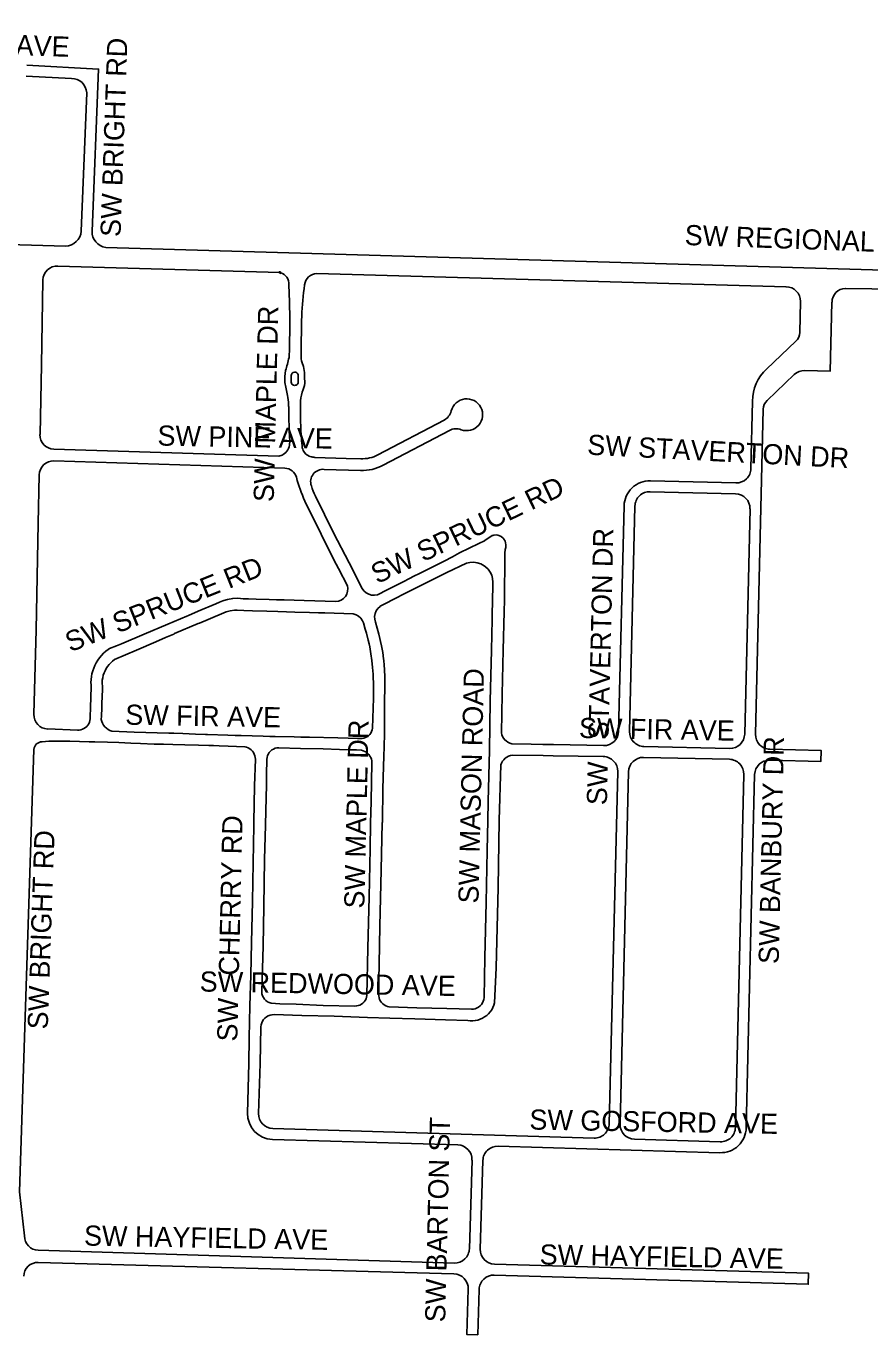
# Model space of a CAD drawing. Extents: x 0 to 712119, y 0 to 761125.
# Drawn here: x 653613 to 655706, y 733634 to 736879 of the extents above; entities that cross this region are included whole.
import ezdxf

# ---------------------------------------------------------------- set-up
doc = ezdxf.new("R2010")
doc.units = 0
doc.layers.add('PAVED ROADS', color=7, linetype='Continuous')
doc.layers.add('street names', color=7, linetype='Continuous')

msp = doc.modelspace()

# ---------------------------------------------------------------- linework, layer by layer
at = {"layer": 'PAVED ROADS'}
for points in [[(657753.4, 736928.9), (657749.7, 736845.1), (657747, 736769.4), (657743.9, 736681.1), (657740.8, 736600.3), (657740.4, 736591.6), (657739.5, 736570.9), (657737.5, 736524.9), (657733.5, 736433.4), (657731.4, 736387.5), (657730.8, 736374.3), (657730.6, 736368.1), (657728.4, 736314.2), (657722.6, 736235.8), (657720.2, 736229), (657715.5, 736222), (657473, 736223.4), (653810.4, 736330.2)], [(653776.8, 736370.3), (653792.4, 736772.4), (653614.5, 736781.6)], [(653613.1, 736754.6), (653725.4, 736748.7)], [(653763.1, 736713.3), (653749.7, 736370.2)], [(653710.8, 736333.1), (652495, 736368.5)], [(653691.7, 736283.5), (653691.7, 736283.6), (654241.9, 736267.6), (654241.8, 736265.5)], [(653647.3, 735865.8), (653650.7, 736039.2), (653654.6, 736249.2)], [(654334, 736265.3), (655497.8, 736232.7)], [(655645, 736228.5), (655646.4, 736228.5), (657007.1, 736211.2)], [(655533.9, 736195.9), (655532.2, 736119.4), (655532.2, 736119.4)], [(655544.3, 736024.7), (655607.7, 736023.2), (655611.9, 736194.3)], [(654267.4, 736158.2), (654267.2, 736148.9), (654265.9, 736070.5)], [(654294.9, 736071), (654296.2, 736148.3), (654296.4, 736160.2)], [(655522.5, 736097.4), (655449.8, 736028.2)], [(654270.6, 735998), (654270.7, 736012.1)], [(654287.9, 736014), (654287.9, 735996.6)], [(654287.9, 736014), (654287.9, 736014)], [(655450.9, 735950.5), (655518.3, 736014.6)], [(655414.8, 735949), (655410.8, 735781.5)], [(654667.5, 735924.7), (654667.5, 735924.7)], [(655422.3, 735122.8), (655441.3, 735928.8)], [(654649.6, 735901.9), (654485.4, 735815.6)], [(654498.9, 735790), (654663.1, 735876.2)], [(654239.6, 735812.2), (653681.6, 735829.6)], [(654254.6, 735782.7), (653681.8, 735800.6)], [(654443, 735805.9), (654407, 735807), (654328.7, 735809.4)], [(653645.2, 735765.8), (653642.8, 735645.5), (653637.4, 735381.8), (653631.9, 735172.3)], [(654352.2, 735779.7), (654442.1, 735776.9)], [(655373.4, 735745.9), (655161.3, 735751.2)], [(655160.7, 735724.2), (655372.9, 735718.9)], [(653816.4, 735333.3), (653819.9, 735335.4), (653837.2, 735342.4), (653849.5, 735347.4), (653905.9, 735371.4), (653964.2, 735395.6), (654011.4, 735415.6), (654015.3, 735417.3), (654039.6, 735427.7), (654083.7, 735446.5), (654092.9, 735450.5), (654100.5, 735453.6), (654103, 735454.4), (654112.8, 735457.3), (654125.5, 735459.5), (654138.3, 735460), (654151.1, 735459), (654164.4, 735458.6), (654183.2, 735458), (654215.7, 735457), (654234.1, 735456.4), (654253, 735455.8), (654302.9, 735454.2), (654381.3, 735451.9), (654387.6, 735452.9), (654394.2, 735455.4), (654400, 735459.3), (654404.8, 735464.5), (654408.3, 735470.5), (654410.3, 735477.3), (654410.8, 735484.3), (654409.7, 735491.2), (654387.7, 735533.6), (654376.3, 735555.7), (654344.5, 735618.8), (654304, 735701.2)], [(655045.4, 735094.7), (654921.2, 735097.1), (654894.9, 735097.6), (654865.6, 735098.2), (654818, 735099.4), (654812.5, 735101), (654807.5, 735103.2), (654803.6, 735106.1), (654800.1, 735108.9), (654797.1, 735112.7), (654794.7, 735116.9), (654792.9, 735121.5), (654791.7, 735126.2), (654794.1, 735222.3), (654796.6, 735331), (654798.8, 735427), (654799.2, 735455.5), (654799.5, 735477.6), (654799.9, 735500.4), (654799.9, 735500.6), (654800.1, 735522.3), (654800.7, 735572.9), (654801.1, 735580.2), (654801.3, 735581.1), (654802.5, 735585.8), (654803.2, 735592.1), (654802.3, 735598.3), (654800.9, 735602), (654799.9, 735604.2), (654798.6, 735606.1), (654796.1, 735609.3), (654791.2, 735613.3), (654785.4, 735615.9), (654782.7, 735616.4), (654779.2, 735617), (654772.8, 735616.5), (654770.9, 735615.9), (654768.8, 735615.3), (654750.4, 735603.1), (654749.9, 735602.8), (654735.6, 735595.8), (654711.9, 735584.1), (654688.3, 735572.4), (654670.2, 735562.8), (654649.6, 735551.9), (654643.2, 735548.6), (654584, 735519.3), (654579.9, 735517.2), (654558.7, 735506.2), (654552.7, 735503.1), (654508.2, 735480.8), (654484.2, 735468.5), (654476.9, 735467.5), (654469.7, 735468), (654462.7, 735470.1), (654456.3, 735473.6), (654450.8, 735478.5), (654446.6, 735484.4), (654446.5, 735484.5), (654426.7, 735523), (654419.7, 735536.8), (654413.9, 735548), (654375, 735622.6), (654330.4, 735713.3)], [(655096.2, 735689.3), (655082.7, 735130.3)], [(655109.7, 735129.8), (655123.2, 735688.6)], [(655408.5, 735681.6), (655395.3, 735123.3)], [(653666.4, 735135.9), (653740.2, 735133), (653744.4, 735133.2), (653748.6, 735133.9), (653752.6, 735135.1), (653756.4, 735136.9), (653760, 735139.3), (653763.1, 735142), (653765.9, 735145.2), (653768.2, 735148.8), (653770, 735152.6), (653771.2, 735156.6), (653771.9, 735160.8), (653772, 735165.6), (653772.6, 735189.2), (653773.8, 735240.8), (653773.9, 735244.5), (653773.7, 735251.6), (653774, 735257.7), (653774, 735258.7), (653774.8, 735265.7), (653776, 735272.7), (653778, 735279.8), (653780.5, 735286.8), (653783.5, 735293.6), (653786.9, 735300.2), (653790.8, 735306.6), (653795.2, 735312.6), (653799.9, 735318.3), (653805.1, 735323.7), (653810.6, 735328.7), (653816.4, 735333.2), (653816.4, 735333.3)], [(653609, 733878.9), (653596.4, 733988.2), (653632.3, 735085.4), (653633, 735089.1), (653634.3, 735092.6), (653636.3, 735095.8), (653638.8, 735098.7), (653641.8, 735101), (653645.2, 735102.7), (653648.8, 735103.8), (653652.5, 735104.2), (653669.6, 735105.8), (653705.1, 735106), (653712.9, 735106), (653721.7, 735105.8), (653769.3, 735104.4), (653783.5, 735104), (653814.4, 735103.1), (653842.7, 735102.3), (653872.2, 735101.1), (653896.8, 735100), (653930.7, 735098.6), (653954, 735097.9), (653976.4, 735097.2)], [(653976.4, 735097.2), (654006.3, 735096.2), (654040.8, 735095.4), (654065.7, 735094.8), (654077.4, 735094.6), (654091.9, 735094.1), (654113.8, 735093.3), (654155.6, 735091.8), (654159.8, 735090.6), (654163.8, 735088.9), (654167.5, 735086.7), (654170.9, 735084), (654174, 735080.9), (654176.6, 735077.4), (654178.7, 735073.6), (654180.3, 735069.6), (654181.3, 735065.4), (654181.8, 735061), (654179.1, 734994.5), (654178, 734905.2), (654177.8, 734896.3), (654176.1, 734804), (654174, 734708.1), (654172.1, 734606), (654170.1, 734525.2), (654168.2, 734449.3), (654166, 734370.3), (654165.3, 734306), (654162.3, 734183.3)], [(654189.5, 734182.5), (654193.6, 734306), (654195.1, 734397.5), (654195.8, 734402.3), (654197.2, 734407), (654199.3, 734411.5), (654202.1, 734415.5), (654205.4, 734419.1), (654209.2, 734422.2), (654213.5, 734424.6), (654218.1, 734426.4), (654222.9, 734427.4), (654227.8, 734427.7), (654296.8, 734425.5), (654377.3, 734423.6), (654459.7, 734420.5), (654515, 734418.8), (654577.1, 734417.1), (654653.4, 734414.4), (654708.2, 734412.9), (654714.5, 734412.1), (654720.7, 734412.1), (654727, 734412.8), (654733.2, 734414.1), (654739.2, 734416), (654744.9, 734418.6), (654750.3, 734421.8), (654755.4, 734425.5), (654760, 734429.8), (654764.2, 734434.5), (654767.8, 734439.6), (654770.9, 734445.2), (654773.3, 734451), (654775.1, 734457), (654778.5, 734543.4), (654783.4, 734742.4), (654786.3, 734909.2), (654786.3, 734909.8), (654790.4, 735046.6), (654792.1, 735051.3), (654794.4, 735055.7), (654797.5, 735059.7), (654801, 735063.2), (654805.1, 735066.1), (654809.6, 735068.4), (654814.4, 735069.9), (654819.3, 735070.6), (654895.5, 735069.8), (654920.2, 735069.5)], [(654920.2, 735069.5), (655044.6, 735067.7)], [(655358, 735087.7), (655145.4, 735092.4)], [(655457.3, 735058.5), (655584.4, 735055.6), (655585, 735082.6), (655458, 735085.5)], [(655144.6, 735065.4), (655357.3, 735060.7)], [(655080.3, 735030.3), (655059.2, 734157)], [(655086.2, 734155.8), (655107.3, 735029.8)], [(655393, 735023.3), (655372.3, 734147.7)], [(655399.3, 734147.1), (655420, 735022.8)], [(655021.7, 734121.4), (654224.9, 734145), (654224.9, 734145)], [(654223.9, 734118), (654683.5, 734104.4)], [(654783.5, 734101.4), (655334, 734085.1)], [(655334.8, 734112.1), (655121.6, 734118.4)], [(654718.9, 734066.8), (654712.5, 733847)], [(654739.5, 733846.2), (654745.9, 734066)], [(654675, 733811.6), (653642.9, 733843.1)], [(653642.8, 733813.1), (654674.2, 733784.6)], [(654774.1, 733781.7), (655552.9, 733759), (655553.7, 733786), (654774.9, 733808.7)], [(654709.6, 733747), (654706.3, 733634.3), (654733.3, 733633.5), (654736.6, 733746.3)]]:
    msp.add_lwpolyline(points, dxfattribs=at)
for points in [[(654769.4, 735446.9), (654769, 735426.6), (654768.6, 735407.7), (654767.3, 735331.7), (654764.3, 735205.2), (654762.3, 735083.3), (654759.3, 734955.9), (654758.3, 734908.6), (654756.6, 734834.7), (654754.2, 734705.9), (654750.8, 734569.4), (654749.1, 734469.6), (654748.4, 734465), (654747, 734460.6), (654744.9, 734456.4), (654742.3, 734452.6), (654739.1, 734449.2), (654735.4, 734446.3), (654731.4, 734444), (654727.1, 734442.3), (654722.5, 734441.3), (654717.9, 734440.9), (654656.7, 734442.6), (654582.1, 734444.2), (654513.4, 734446.6), (654509.1, 734447.7), (654505, 734449.4), (654501.1, 734451.7), (654497.6, 734454.5), (654494.5, 734457.7), (654491.9, 734461.3), (654489.8, 734465.3), (654488.3, 734469.5), (654487.4, 734473.9), (654487, 734478.3), (654488.3, 734553), (654490.6, 734646.8), (654493.3, 734786.7), (654496.4, 734903.1), (654496.5, 734905.2), (654498.1, 734989.5), (654498.5, 735013.4), (654498.6, 735016.3), (654500.1, 735068.8), (654500.8, 735091.6), (654501.7, 735124.4), (654502.1, 735175.4), (654502.2, 735197.7), (654502.6, 735246.1), (654502.7, 735262.1), (654502.4, 735269.3), (654502.2, 735278.2), (654501.9, 735283.1), (654501.1, 735294.1), (654499.9, 735305.8), (654499.5, 735310.1), (654497.3, 735325.9), (654494.6, 735341.7), (654488, 735371.2), (654479.9, 735400.4), (654477.5, 735407.9), (654477.2, 735415.2), (654478.4, 735422.3), (654481.2, 735429.1), (654485.4, 735435), (654490.7, 735439.9), (654491.4, 735440.4), (654504.4, 735447.1), (654524.9, 735457.6), (654554.2, 735472.6), (654605.2, 735498.1), (654656.6, 735524.1), (654705, 735547.2), (654713.9, 735549.1), (654723.1, 735549.3), (654732.1, 735548), (654740.8, 735545.1), (654748.9, 735540.7), (654752.6, 735538), (654758.9, 735532), (654764, 735525), (654767.7, 735517.1), (654769.9, 735508.8), (654770.6, 735500.1), (654770.6, 735499.2)], [(654153.2, 735429.8), (654174.8, 735429.2), (654210.1, 735428.2), (654237, 735427.2), (654258.4, 735426.5), (654279.6, 735425.8), (654315.9, 735424.7), (654338.4, 735424), (654353.8, 735423.6), (654424.3, 735421.4), (654431.3, 735419.2), (654437.6, 735415.4), (654443, 735410.4), (654447.1, 735404.4), (654449.5, 735398.8), (654454.1, 735383.5), (654457.2, 735373.2), (654461.4, 735356.1), (654463.5, 735347.2), (654465.2, 735339.4), (654468.1, 735322.5), (654470.4, 735305.6), (654472.2, 735288.6), (654473.5, 735271.6), (654474.1, 735258.7), (654474.3, 735254.5), (654474.5, 735237.4), (654474.4, 735212.6), (654473.9, 735187.7), (654473.3, 735162.9), (654472.3, 735138), (654471.4, 735133.7), (654469.9, 735129.5), (654467.8, 735125.6), (654465.1, 735122.1), (654462, 735119), (654458.4, 735116.4), (654454.4, 735114.4), (654450.2, 735113), (654445.8, 735112.2), (654441.4, 735112.1), (654435.2, 735112.3), (654411.5, 735112.9), (654386.2, 735113.7), (654315.7, 735115.4), (654294.4, 735115.9), (654277.4, 735116.2), (654230.7, 735117.2), (654217.3, 735117.6), (654200.5, 735118), (654146.3, 735119.4), (654131.6, 735120), (654113.3, 735120.6), (654063.1, 735122.4), (654058, 735122.6), (654033.4, 735123.4), (654001.6, 735124.4), (653979.6, 735125.1), (653966.6, 735125.5), (653881.2, 735127.9), (653825.6, 735130.8), (653820.7, 735132.5), (653816.1, 735134.8), (653811.9, 735137.8), (653808.2, 735141.4), (653805, 735145.4), (653802.4, 735149.9), (653800.6, 735154.7), (653799.4, 735159.7), (653799.6, 735167.4), (653800.4, 735188.7), (653800.7, 735199), (653802, 735234.1), (653801.9, 735256.9), (653802.8, 735263), (653804.3, 735269), (653806.2, 735274.8), (653808.7, 735280.4), (653811.6, 735285.8), (653814.9, 735291), (653818.7, 735295.8), (653822.9, 735300.3), (653827.4, 735304.4), (653832.4, 735308.2), (653886.7, 735331.6), (653934.9, 735352.2), (653959, 735362.6), (653979.2, 735371.4), (653981.2, 735372.3), (654039.8, 735397.1), (654043, 735398.4), (654064.4, 735407.4), (654108.9, 735426), (654119.2, 735428.9), (654129.8, 735430.3), (654136.4, 735430.3)], [(654197.3, 734483.8), (654200.5, 734598.3), (654202.3, 734696), (654204.5, 734812.6), (654206.4, 734897), (654207.3, 734932.7), (654208.8, 734997.7), (654209.4, 735022.4), (654210.3, 735061.1), (654210.7, 735065.5), (654211.9, 735069.9), (654213.7, 735074), (654216.1, 735077.7), (654219.1, 735081.1), (654222.6, 735083.9), (654226.4, 735086.2), (654230.6, 735087.9), (654234.9, 735088.9), (654239.4, 735089.3), (654293.7, 735087.8), (654349.9, 735086.5), (654390.4, 735085.3), (654412.8, 735084.5), (654432.6, 735083.8), (654445, 735083.3), (654449.1, 735082.1), (654453.1, 735080.3), (654456.8, 735078.1), (654460.1, 735075.4), (654463.1, 735072.2), (654465.6, 735068.7), (654467.7, 735064.9), (654469.2, 735060.9), (654470.2, 735056.7), (654470.7, 735052.4), (654468.4, 734956.2), (654467.3, 734902.5), (654466, 734838.6), (654463.4, 734719.6), (654460.9, 734592.7), (654458.3, 734475.3), (654457.4, 734471), (654456, 734466.8), (654454, 734462.9), (654451.4, 734459.4), (654448.4, 734456.2), (654444.9, 734453.6), (654441, 734451.4), (654436.9, 734449.9), (654432.6, 734449), (654428.2, 734448.7), (654350, 734450.3), (654282.8, 734453.5), (654242.5, 734454.3), (654220.6, 734455.7), (654215.9, 734457.2), (654211.6, 734459.4), (654207.6, 734462.3), (654204.2, 734465.8), (654201.4, 734469.9), (654199.3, 734474.3), (654197.9, 734479)]]:
    msp.add_lwpolyline(points, close=True, dxfattribs=at)
for centre, radius, start, end in [((653726.2, 736711.8), 36.9, 2.3097, 91.2272), ((653709, 736374), 40.9, 272.5206, 354.6783), ((653815, 736368.2), 38.3, 176.8618, 263.0851), ((653689.7, 736248.6), 35, 86.7173, 178.9132), ((654242.2, 736267.7), 2.18, 266.4905, 171.3016), ((654236, 736239.8), 28.5, 5.6361, 81.9022), ((654240.6, 736241.8), 23.8, 86.4905, 86.991), ((672977.8, 736865.5), 18723.8, 181.90632, 182.16485), ((655406.7, 736096), 1112.1, 172.6981, 176.6943), ((654335.6, 736233.1), 32.3, 92.8965, 172.3549), ((655497.3, 736196.1), 36.6, 359.7573, 89.2549), ((655647.1, 736193.4), 35.2, 93.335, 178.507), ((655500.7, 736120.2), 31.5, 313.6162, 358.616), ((653816.6, 736160), 460.1, 342.8717, 347.0977), ((653084, 736134.4), 1183.6, 356.263, 356.9014), ((655394.2, 736095.6), 1099.7, 181.2802, 181.9123), ((654350.2, 736059.6), 55, 180.7019, 201.6906), ((654426.3, 736000.3), 171.7, 171.8989, 181.6508), ((654279.4, 736012), 8.73, 12.875, 179.5861), ((654244, 736017.4), 59.3, 2.3081, 21.6906), ((652947.5, 735965.1), 1356.8, 1.4121, 2.3081), ((655518.6, 735950.4), 103.9, 131.5079, 180.7576), ((655543.4, 735988.2), 36.5, 88.6163, 133.6163), ((653237, 735763.7), 1043.6, 10.9978, 12.8247), ((654279.2, 735996.6), 8.69, 170.8312, 359.7563), ((654391, 735940.7), 98, 157.925, 174.6298), ((654251.6, 735997.2), 52.4, 337.9296, 1.4121), ((654140.2, 735940.6), 123.3, 0.3133, 10.3822), ((657236.8, 735955.6), 2943.5, 180.1106, 181.4867), ((654705.8, 735915.1), 39.5, 249.5208, 165.9001), ((655472.3, 735928), 31, 133.6163, 178.6685), ((653678.7, 735877.3), 588.3, 5.3522, 6.2395), ((657236.8, 735955.6), 2972.5, 180.4507, 181.4867), ((654633.1, 735933.3), 35.5, 297.7104, 345.9001), ((654748.8, 735891), 454.6, 181.4867, 187.3523), ((654679.6, 735844.8), 35.5, 69.5208, 117.7104), ((653682.7, 735865.1), 35.5, 178.8516, 268.2174), ((654748.8, 735891), 483.6, 181.4867, 184.659), ((653713.3, 735870.8), 553.9, 357.1573, 358.0219), ((654233.9, 735844.7), 33, 279.8573, 300.1908), ((654232.4, 735845.1), 34.1, 302.1193, 357.1804), ((654332.5, 735842.7), 36, 195.887, 216.4803), ((654325.2, 735837.3), 26.9, 216.4552, 257.8001), ((654445.6, 735891.3), 85.5, 268.2175, 297.7104), ((653680.7, 735765.1), 35.5, 88.2174, 178.8516), ((654253.8, 735752.2), 30.5, 14.6958, 88.5777), ((654669, 737853.7), 2072.4, 260.2918, 260.5476), ((654445.6, 735891.3), 114.5, 268.2174, 297.7104), ((655374.4, 735782.4), 36.5, 268.5672, 358.6492), ((654742.4, 735888.5), 476.8, 195.6425, 203.1345), ((654349.4, 735749), 30.8, 84.8334, 199.4562), ((655159.7, 735687.7), 63.5, 88.5672, 178.6163), ((654748.8, 735891), 454.6, 199.5641, 203.011), ((655159.5, 735688), 36.3, 88.1689, 179.0134), ((655372, 735682.4), 36.5, 358.6492, 88.5672), ((653667.4, 735171.3), 35.5, 178.5163, 268.3536), ((655046.2, 735131.1), 36.5, 268.7241, 358.6163), ((655146.2, 735128.9), 36.5, 178.6163, 268.7241), ((655358.8, 735124.2), 36.5, 268.7241, 358.6492), ((655458.8, 735122), 36.5, 178.6492, 268.7236), ((655043.8, 735031.2), 36.5, 358.6163, 88.7241), ((655458.3, 735097.1), 11.7, 268.7235, 268.7241), ((655143.8, 735028.9), 36.5, 88.7241, 178.6163), ((655356.5, 735024.2), 36.5, 358.6492, 88.7241), ((655456.5, 735022), 36.5, 88.7241, 178.6492), ((654225.8, 734181.5), 63.5, 178.3025, 268.3025), ((654225.9, 734181.5), 36.5, 178.3025, 268.3025), ((655022.7, 734157.8), 36.5, 268.3025, 358.6177), ((655122.7, 734154.9), 36.5, 178.6163, 268.3025), ((655335.8, 734148.6), 63.5, 268.3025, 358.6492), ((655335.8, 734148.6), 36.5, 268.3025, 358.6492), ((654682.4, 734067.9), 36.5, 358.3333, 88.3025), ((654782.4, 734064.9), 36.5, 88.3006, 178.3333), ((653644, 733878.1), 35, 178.7487, 268.3333), ((654676, 733848.1), 36.5, 268.3331, 358.3347), ((654776, 733845.2), 36.5, 178.3333, 268.3333), ((653641.8, 733778.1), 35, 88.3333, 178.7487), ((654673.1, 733748.1), 36.5, 358.3333, 88.3333), ((654773.1, 733745.2), 36.5, 88.3333, 178.3333)]:
    msp.add_arc(centre, radius, start, end, dxfattribs=at)

# ---------------------------------------------------------------- texts
at = {"layer": 'street names'}
for s, rotation, p in [('SW YUCCA AVE', 357.9335, (653207.4, 736821)), ('SW BRIGHT RD', 87.9838, (653847, 736355.4)), ('SW REGIONAL AIRPORT BLVD', 357.9335, (655245.9, 736336.2)), ('SW  MAPLE DR', 88.6343, (654227, 735698.3)), ('SW PINE AVE', 358.9838, (653938.4, 735838.7)), ('SW STAVERTON DR', 357.0122, (655003.9, 735816.3)), ('SW SPRUCE RD', 25.6131, (654483.8, 735494.6)), ('SW   STAVERTON DR', 88.6343, (655053.5, 734946.5)), ('SW SPRUCE RD', 21.7827, (653722.4, 735325.7)), ('SW MASON ROAD', 88.6343, (654734.9, 734702.8)), ('SW FIR AVE', 358.9838, (653858.5, 735146.5)), ('SW MAPLE DR', 88.6343, (654451.7, 734690.3)), ('SW FIR AVE', 358.9838, (654983.9, 735113.6)), ('SW BANBURY DR', 88.6343, (655479.6, 734552.6)), ('SW   CHERRY RD', 88.6343, (654136.6, 734360.5)), ('SW BRIGHT RD', 87.9838, (653666.4, 734390.3)), ('SW REDWOOD AVE', 358.9838, (654043.1, 734484.9)), ('SW GOSFORD AVE', 358.9838, (654861, 734142.6)), ('SW BARTON ST', 88.6343, (654652.4, 733664.1)), ('SW HAYFIELD AVE', 358.9838, (653756.2, 733854.8)), ('SW HAYFIELD AVE', 358.9838, (654886.4, 733808))]:
    msp.add_text(s, height=50, rotation=rotation, dxfattribs=at).set_placement(p)

doc.saveas('drawing.dxf')
